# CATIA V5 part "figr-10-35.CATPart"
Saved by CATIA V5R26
Part number: Part1
Bounding box of the stored display mesh (mm): x -80 to 120, y 0 to 190, z 0 to 170
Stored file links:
  D:\_Deepak\CATIA\CATIA V5-6R2016_Deepak\Resources\Part files\Partfiles\c10_catia_v5_6r2016_prt\figr-10-35.CATPart
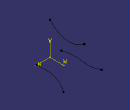
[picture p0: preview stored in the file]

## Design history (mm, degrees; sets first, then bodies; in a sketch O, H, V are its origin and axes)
Set1
  Sketch1 on xy-plane, origin (0, 0, 0), H (1, 0, 0), V (0, 1, 0)
    spline S1 through (-60, 0) (-70, 70) (-70, 170) (-80, 190)
  Sketch2 on yz-plane, origin (0, 0, 0), H (0, 1, 0), V (0, 0, 1)
    spline S1 through (0, 170) (100, 120) (180, 150)
  Sketch3 on xy-plane, origin (0, 0, 0), H (1, 0, 0), V (0, 1, 0)
    spline S1 through (70, 0) (70, 80) (120, 190)
Body1 (main body)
